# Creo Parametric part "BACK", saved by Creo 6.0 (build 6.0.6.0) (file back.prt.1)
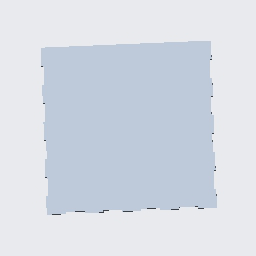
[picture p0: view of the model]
Units: Inch lbm Second (Pro/E Default); INCH, POUND, SECS

Created from: INLBS_PART_SOLID.PRT

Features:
  1. datum plane "RIGHT"
  2. datum plane "TOP"
  3. datum plane "FRONT"
  4. coordinate system
  5. sketch "Sketch 1"
  6. extrusion "Extrude 1"

Surfaces: 54 plane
